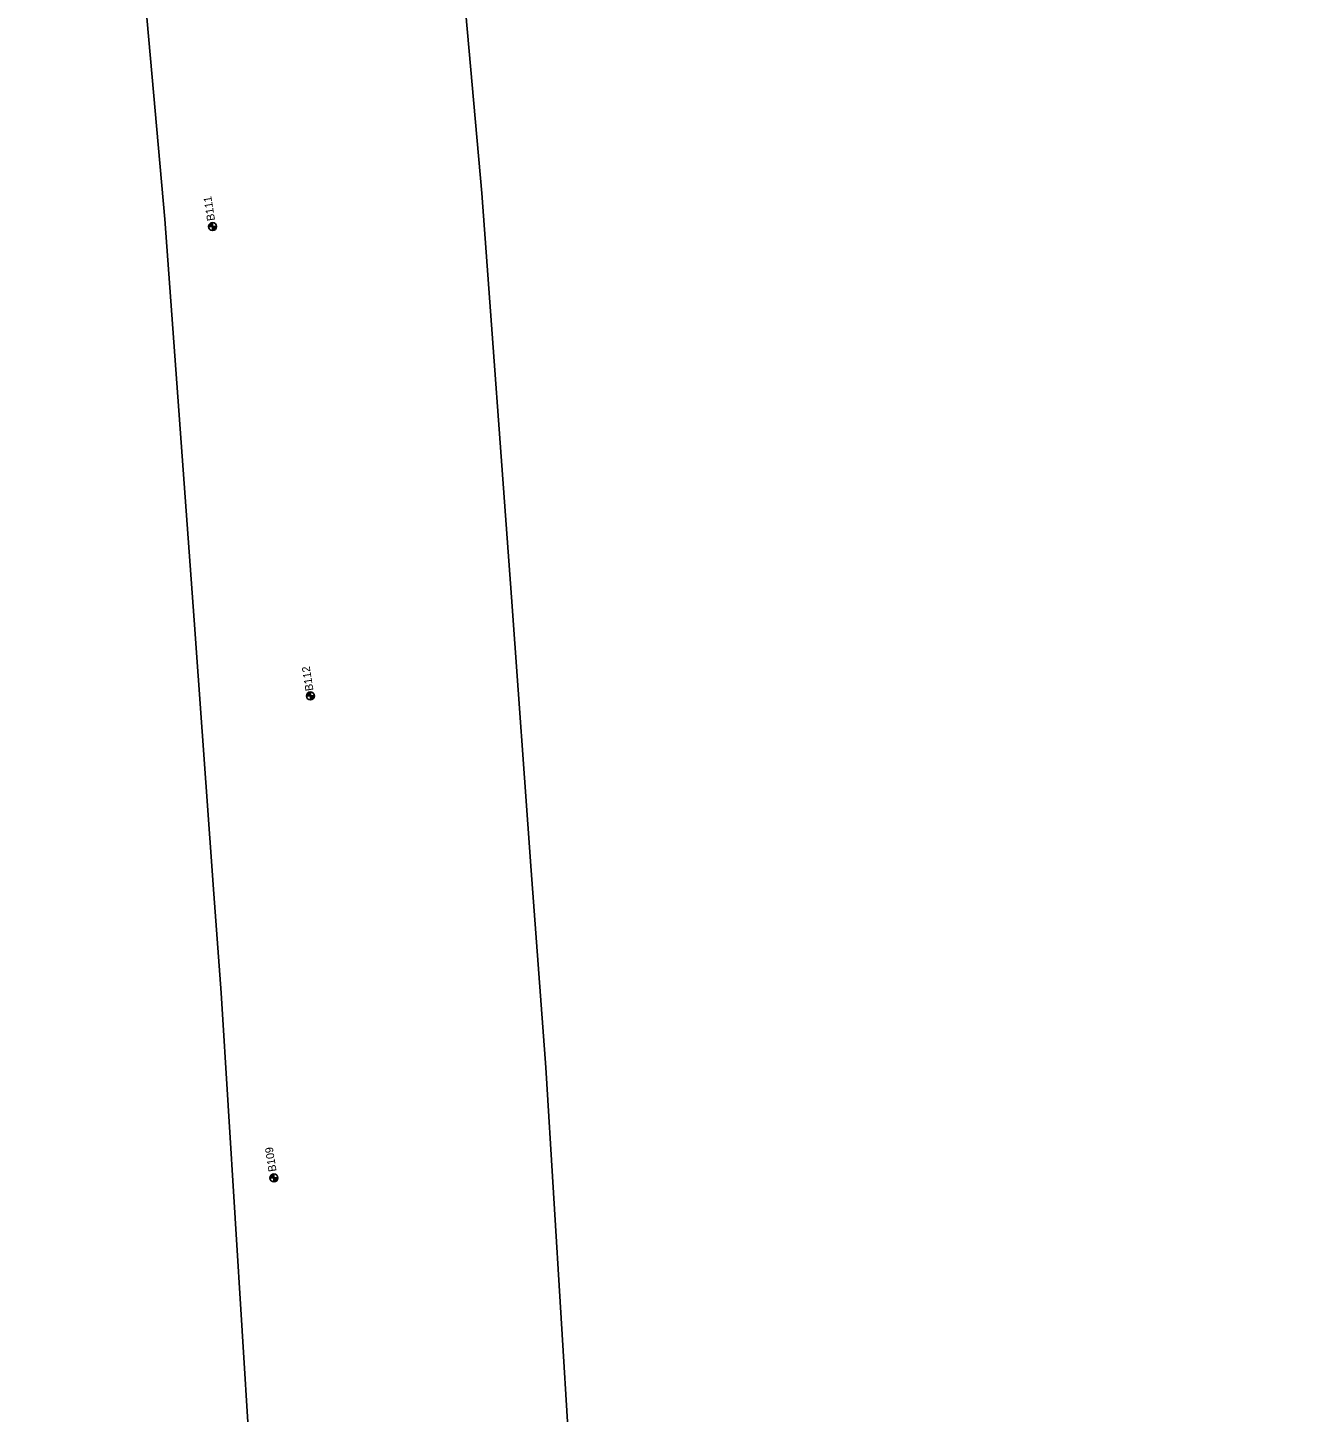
# Model space of a CAD drawing. Extents: x 327762 to 372792, y 127949 to 259367.
# Drawn here: x 355040 to 356660, y 188696 to 190437 of the extents above; entities that cross this region are included whole.
import ezdxf

# ---------------------------------------------------------------- set-up
doc = ezdxf.new("R2010")
doc.units = 0
for name, color, linetype in [('E_SOIL_BORE1 [KAPUR_CADDS_LEVELS]', 7, 'Continuous'), ('E_SOIL_BORE2 [KAPUR_CADDS_LEVELS]', 7, 'Continuous'), ('P_MARK', 7, 'Continuous'), ('P_TC', 7, 'Continuous')]:
    doc.layers.add(name, color=color, linetype=linetype)

msp = doc.modelspace()

# ---------------------------------------------------------------- linework, layer by layer
at = {"layer": 'P_MARK'}
for p, q in [((355267.7, 190187.1), (355277.7, 190187.1)), ((355272.7, 190192.1), (355272.7, 190182.1)), ((355395.7, 189602.1), (355395.7, 189592.1)), ((355390.7, 189597.1), (355400.7, 189597.1)), ((355349.9, 188996.1), (355349.9, 188986.1)), ((355344.9, 188991.1), (355354.9, 188991.1))]:
    msp.add_line(p, q, dxfattribs=at)
for centre in [(355272.7, 190187.1), (355395.7, 189597.1), (355349.9, 188991.1)]:
    msp.add_circle(centre, 5, dxfattribs=at)
for centre, radius, start, end in [((355272.7, 190187.1), 4.5, 89.9869, 179.9869), ((355272.7, 190187.1), 4, 89.9869, 179.9869), ((355272.7, 190187.1), 3.5, 89.9869, 179.9869), ((355272.7, 190187.1), 3, 89.9869, 179.9869), ((355272.7, 190187.1), 2.5, 89.9869, 179.9869), ((355272.7, 190187.1), 2, 89.9869, 179.9869), ((355272.7, 190187.1), 1.5, 89.9869, 179.9869), ((355272.7, 190187.1), 1, 89.9869, 179.9869), ((355272.7, 190187.1), 0.5, 89.9869, 179.9869), ((355272.7, 190187.1), 4.5, 269.9869, 359.9869), ((355272.7, 190187.1), 4, 269.9869, 359.9869), ((355272.7, 190187.1), 3.5, 269.9869, 359.9869), ((355272.7, 190187.1), 3, 269.9869, 359.9869), ((355272.7, 190187.1), 2.5, 269.9869, 359.9869), ((355272.7, 190187.1), 2, 269.9869, 359.9869), ((355272.7, 190187.1), 1.5, 269.9869, 359.9869), ((355272.7, 190187.1), 1, 269.9869, 359.9869), ((355272.7, 190187.1), 0.5, 269.9869, 359.9869), ((355395.7, 189597.1), 4.5, 89.9869, 179.9869), ((355395.7, 189597.1), 4, 89.9869, 179.9869), ((355395.7, 189597.1), 3.5, 89.9869, 179.9869), ((355395.7, 189597.1), 3, 89.9869, 179.9869), ((355395.7, 189597.1), 2.5, 89.9869, 179.9869), ((355395.7, 189597.1), 2, 89.9869, 179.9869), ((355395.7, 189597.1), 1.5, 89.9869, 179.9869), ((355395.7, 189597.1), 1, 89.9869, 179.9869), ((355395.7, 189597.1), 0.5, 89.9869, 179.9869), ((355395.7, 189597.1), 4.5, 269.9869, 359.9869), ((355395.7, 189597.1), 4, 269.9869, 359.9869), ((355395.7, 189597.1), 3.5, 269.9869, 359.9869), ((355395.7, 189597.1), 3, 269.9869, 359.9869), ((355395.7, 189597.1), 2.5, 269.9869, 359.9869), ((355395.7, 189597.1), 2, 269.9869, 359.9869), ((355395.7, 189597.1), 1.5, 269.9869, 359.9869), ((355395.7, 189597.1), 1, 269.9869, 359.9869), ((355395.7, 189597.1), 0.5, 269.9869, 359.9869), ((355349.9, 188991.1), 4.5, 89.9869, 179.9869), ((355349.9, 188991.1), 4, 89.9869, 179.9869), ((355349.9, 188991.1), 3.5, 89.9869, 179.9869), ((355349.9, 188991.1), 3, 89.9869, 179.9869), ((355349.9, 188991.1), 2.5, 89.9869, 179.9869), ((355349.9, 188991.1), 2, 89.9869, 179.9869), ((355349.9, 188991.1), 1.5, 89.9869, 179.9869), ((355349.9, 188991.1), 1, 89.9869, 179.9869), ((355349.9, 188991.1), 0.5, 89.9869, 179.9869), ((355349.9, 188991.1), 4.5, 269.9869, 359.9869), ((355349.9, 188991.1), 4, 269.9869, 359.9869), ((355349.9, 188991.1), 3.5, 269.9869, 359.9869), ((355349.9, 188991.1), 3, 269.9869, 359.9869), ((355349.9, 188991.1), 2.5, 269.9869, 359.9869), ((355349.9, 188991.1), 2, 269.9869, 359.9869), ((355349.9, 188991.1), 1.5, 269.9869, 359.9869), ((355349.9, 188991.1), 1, 269.9869, 359.9869), ((355349.9, 188991.1), 0.5, 269.9869, 359.9869)]:
    msp.add_arc(centre, radius, start, end, dxfattribs=at)
at = {"layer": 'P_TC'}
for p, q in [((355471.2, 186190.8), (355283.6, 189224)), ((355691.8, 189129.9), (355870.5, 186215.5))]:
    msp.add_line(p, q, dxfattribs=at)
for points in [[(355283.6, 189224), (355274.3, 189348.2), (355249.7, 189692.4), (355212.6, 190196.5), (355174, 190629), (355143, 191045.2), (355065.1, 191886.3), (355040.4, 192233.4), (355074.6, 192700.4), (355130.4, 193038.8), (355243.3, 193407.8), (355370.8, 193719.1), (355556, 194116.5), (355747.6, 194472.4), (355922.8, 194827.6), (356106.3, 195206.2), (356289.3, 195658.8)], [(356660.1, 195508.9), (356472.1, 195043.8), (356282.2, 194652), (356103.2, 194289), (355913.6, 193937), (355737.4, 193558.7), (355620.5, 193273.2), (355520.7, 192947.3), (355472.2, 192653.1), (355441.4, 192233), (355463.8, 191918.9), (355541.6, 191078.5), (355572.6, 190661.6), (355611.3, 190229), (355648.6, 189721.3), (355673.2, 189377.4), (355691.8, 189129.9)]]:
    msp.add_lwpolyline(points, dxfattribs=at)

# ---------------------------------------------------------------- texts
at = {"layer": 'E_SOIL_BORE1 [KAPUR_CADDS_LEVELS]'}
for s, p in [('B111', (355275.9, 190195)), ('B112', (355399.6, 189604.1))]:
    msp.add_text(s, height=10, rotation=98.957, dxfattribs=at).set_placement(p)
at = {"layer": 'E_SOIL_BORE2 [KAPUR_CADDS_LEVELS]'}
msp.add_text('B109', height=10, rotation=98.957, dxfattribs=at).set_placement((355353.2, 188999.7))

doc.saveas('drawing.dxf')
